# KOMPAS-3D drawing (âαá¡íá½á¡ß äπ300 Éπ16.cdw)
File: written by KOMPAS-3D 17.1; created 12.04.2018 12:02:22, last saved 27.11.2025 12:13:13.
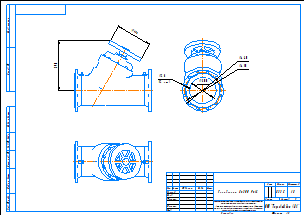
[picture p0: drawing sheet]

Sheet 1: A3, landscape

Title block, sheet 1: name: Гранбаланс Ду300 Ру16; material: Сталь 20  ГОСТ 1050-2013; mass: 833,5; sheets: 1; sheet format: A3; stored path: C:\Users\kka\KOMPAS_Work\!Trash\КМ125 КМ127 КМ225Ф Двухходовые клапана\КМ125Ф + PSL\KOMPAS 2D\Гранрег КМ125Ф Ду32 Ру16.cdw

Views: Спереди 1, Спереди
Referenced files in C:\Users\mipv\Desktop\КБЧ\Имеющиеся\: Гранбаланс Ду300 Ру16  серия 10.m3d
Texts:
  kka
  adl
  Рама для чертежей
  Лит-Масса-Масштаб
  Материал-Предприятие
  Масштаб
  Изм.
  Лист
  № докум.
  Подп.
  Дата
  Лит.
  Разраб.
  Пров.
  Т.контр.
  Листов
  Внимание! Данный продукт является объектом авторского права ООО «Торговый Дом АДЛ».
  Запрещается изменение, копирование, распространение
  (в том числе путем копирования на другие сайты и ресурсы в Интернете)
  или любое иное использование информации и объектов без предварительного
  согласия правообладателя (ООО «Торговый Дом АДЛ»).
  Н.контр.
  Утв.
  ООО "Торговый дом АДЛ"
  Изменение
  Номер документа
  Подпись
  Обозначение документа
  Наименование изделия
  Масса изделия по ГОСТ 2.109-73
  Порядковый номер листа
  Общее количество листов в документе
  Характер работы, выполненной лицом, подписавшим документ
  Наименование или индекс предприятия, выпускающего документ
  Инв. № подл.
  Подп. и дата
  Взам. инв. №
  Инв. № дубл.
  Инвентарный номер подлинника по ГОСТ 2.501-68
  Подпись принявшего подлинник в отдел технической документации
  Инвентарный номер подлинника, взамен которого выпущен данный подлинник
  Инвентарный номер дубликата по ГОСТ 2.502-68
  Подпись принявшего дубликат в отдел технической документации
  Справ. №
  Перв. примен.
  Обозначение документа, взамен или на основании которого выпущен данный документ
  Обозначение документа, в котором впервые записан данный документ
  Подпись лица, копировавшего чертеж
  Обозначение формата листа
  !Рама для чертежа
Dimensions and other numbers on the sheet: 590; 400; 1:8; 1; 833,5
